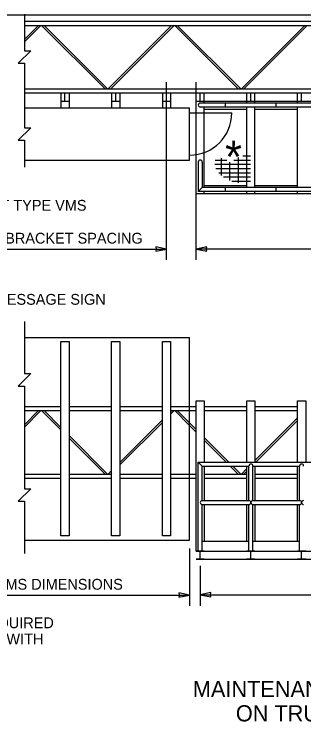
# Model space of a CAD drawing. Extents: x 99862 to 103151, y 100000 to 105076.
# Drawn here: x 100607 to 101035, y 101019 to 102077 of the extents above; entities that cross this region are included whole.
import ezdxf

# ---------------------------------------------------------------- set-up
doc = ezdxf.new("R2010")
doc.units = 0
for name, color, linetype in [('Level 1', 7, 'Continuous'), ('Level 15', 7, 'Continuous'), ('Level 18', 7, 'Continuous'), ('Level 2', 7, 'Continuous'), ('Level 20', 7, 'Continuous'), ('Level 22', 7, 'Continuous'), ('Level 23', 7, 'Continuous'), ('Level 26', 7, 'Continuous'), ('Level 27', 7, 'Continuous'), ('Level 7', 7, 'Continuous')]:
    doc.layers.add(name, color=color, linetype=linetype)

msp = doc.modelspace()

# ---------------------------------------------------------------- linework, layer by layer
at = {"layer": 'Level 1'}
msp.add_lwpolyline([(99862, 99999.5), (103151, 99999.5), (103151, 102075.5), (99862, 102075.5)], close=True, dxfattribs=at)
at = {"layer": 'Level 15'}
for p, q in [((100832, 101713.3), (100832, 101976.3)), ((100876, 101713.3), (100876, 101976.3)), ((100300.8, 101729.3), (100832, 101729.3)), ((101557, 101729.3), (100876, 101729.3)), ((100622.1, 101474), (100622.1, 101426.7)), ((100866.3, 101286.2), (100866.3, 101201)), ((100882, 101260.4), (100882, 101201)), ((100266.8, 101217), (100866.3, 101217)), ((100882, 101217.6), (101557, 101217.6))]:
    msp.add_line(p, q, dxfattribs=at)
for points in [[(100622.1, 102076.7), (100622.1, 102022.7), (100631.3, 102022.7), (100612.8, 102004.2), (100622.1, 102004.2), (100622.1, 101951.9)], [(100622.1, 101961.1), (100622.1, 101908.9), (100631.3, 101908.9), (100612.8, 101890.3), (100622.1, 101890.3), (100622.1, 101850.3)], [(100622.1, 101622.1), (100622.1, 101544.8), (100631.3, 101544.8), (100612.8, 101526.3), (100622.1, 101526.3), (100622.1, 101474)], [(100622.1, 101426.7), (100622.1, 101374.4), (100631.3, 101374.4), (100612.8, 101355.8), (100622.1, 101355.8), (100622.1, 101278.6)]]:
    msp.add_lwpolyline(points, dxfattribs=at)
for points in [[(100832, 101729.3), (100816.3, 101732.4), (100817.1, 101729.3), (100816.3, 101726.2)], [(100876, 101729.3), (100891.8, 101726.2), (100891, 101729.3), (100891.8, 101732.4)], [(100866.3, 101217), (100850.6, 101220.1), (100851.3, 101217), (100850.6, 101213.9)], [(100882, 101217.6), (100897.8, 101214.5), (100897, 101217.6), (100897.8, 101220.6)]]:
    msp.add_lwpolyline(points, close=True, dxfattribs=at)
at = {"layer": 'Level 18'}
for p, q in [((100876, 101948.3), (100876, 101960.3)), ((100888, 101948.3), (100888, 101960.3)), ((100951, 101948.3), (100951, 101960.3)), ((100963, 101948.3), (100963, 101960.3)), ((101026, 101948.3), (101026, 101960.3))]:
    msp.add_line(p, q, dxfattribs=at)
at = {"layer": 'Level 2'}
for p, q in [((100676, 101960.3), (100676, 101938.3)), ((100688, 101960.3), (100688, 101938.3)), ((100751, 101960.3), (100751, 101938.3)), ((100763, 101960.3), (100763, 101938.3)), ((100826, 101960.3), (100826, 101938.3)), ((100838, 101960.3), (100838, 101938.3)), ((100876, 101811.3), (100876, 101948.3)), ((100876, 101948.3), (101563, 101948.3)), ((100888, 101945.3), (100888, 101948.3)), ((100951, 101945.3), (100951, 101948.3)), ((100963, 101945.3), (100963, 101948.3)), ((101026, 101945.3), (101026, 101948.3)), ((100622.1, 101938.3), (100866.3, 101938.3)), ((100866.3, 101860.8), (100866.3, 101938.3)), ((101507.3, 101945.3), (100882, 101945.3)), ((101507.3, 101939.3), (100882, 101939.3)), ((100888, 101820.4), (100888, 101939.3)), ((100888, 101936.3), (100951, 101936.3)), ((100919.5, 101939.3), (100919.5, 101945.3)), ((100951, 101820.4), (100951, 101939.3)), ((100963, 101820.4), (100963, 101939.3)), ((100963, 101936.3), (101026, 101936.3)), ((100994.5, 101939.3), (100994.5, 101945.3)), ((101026, 101820.4), (101026, 101939.3)), ((100866.3, 101930.8), (100928.8, 101930.8)), ((100622.1, 101860.8), (100866.3, 101860.8)), ((100879, 101858), (100879, 101814.4)), ((100885, 101858), (100885, 101820.4)), ((100885, 101820.4), (100879, 101814.4)), ((101554.1, 101820.4), (100885, 101820.4)), ((100888, 101823.3), (100951, 101823.3)), ((100919.5, 101814.4), (100919.5, 101820.4)), ((100963, 101823.3), (101026, 101823.3)), ((100994.5, 101814.4), (100994.5, 101820.4)), ((100876, 101811.3), (101563, 101811.3)), ((101560.1, 101814.4), (100879, 101814.4)), ((100888, 101811.3), (100888, 101814.4)), ((100951, 101811.3), (100951, 101814.4)), ((100963, 101811.3), (100963, 101814.4)), ((101026, 101811.3), (101026, 101814.4)), ((100622.1, 101598.5), (100866.3, 101598.5)), ((100866.3, 101298.5), (100866.3, 101598.5)), ((100879, 101414), (100885, 101408)), ((100622.1, 101298.5), (100866.3, 101298.5))]:
    msp.add_line(p, q, dxfattribs=at)
for points in [[(100676, 101592.5), (100688, 101592.5), (100688, 101304.5), (100676, 101304.5)], [(100751, 101592.5), (100763, 101592.5), (100763, 101304.5), (100751, 101304.5)], [(100826, 101592.5), (100838, 101592.5), (100838, 101304.5), (100826, 101304.5)]]:
    msp.add_lwpolyline(points, close=True, dxfattribs=at)
for centre, radius, start, end in [((100882, 101942.3), 3, 90, 270), ((100866.3, 101930.8), 62.5, 270, 0), ((100882, 101858), 3, 0, 180), ((100957, 101408), 3, 0, 180), ((101032, 101408), 3, 0, 180), ((100885, 101354), 3, 90, 270), ((100954, 101354), 3, 270, 90), ((100960, 101354), 3, 90, 270), ((101029, 101354), 3, 270, 90), ((101035, 101354), 3, 90, 270)]:
    msp.add_arc(centre, radius, start, end, dxfattribs=at)
at = {"layer": 'Level 22'}
for points in [[(100888, 101282), (100876, 101282), (100876, 101504.5), (100888, 101504.5), (100888, 101414)], [(100951, 101414), (100951, 101504.5), (100963, 101504.5), (100963, 101414)], [(101026, 101414), (101026, 101504.5), (101038, 101504.5), (101038, 101414)], [(100888, 101408), (100888, 101357)], [(100951, 101357), (100951, 101408)], [(100963, 101408), (100963, 101357)], [(101026, 101357), (101026, 101408)], [(100888, 101351), (100888, 101297)], [(100951, 101297), (100951, 101351)], [(100963, 101351), (100963, 101297)], [(101026, 101297), (101026, 101351)]]:
    msp.add_lwpolyline(points, dxfattribs=at)
at = {"layer": 'Level 23'}
for p, q in [((100676, 101960.3), (100688, 101960.3)), ((100682, 101948.3), (100682, 101960.3)), ((100751, 101960.3), (100763, 101960.3)), ((100757, 101948.3), (100757, 101960.3)), ((100826, 101960.3), (100838, 101960.3)), ((100832, 101948.3), (100832, 101960.3)), ((100876, 101960.3), (100888, 101960.3)), ((100882, 101948.3), (100882, 101960.3)), ((100951, 101960.3), (100963, 101960.3)), ((100957, 101948.3), (100957, 101960.3)), ((101026, 101960.3), (101038, 101960.3)), ((101032, 101948.3), (101032, 101960.3)), ((100676, 101948.3), (100688, 101948.3)), ((100751, 101948.3), (100763, 101948.3)), ((100826, 101948.3), (100838, 101948.3)), ((100876, 101948.3), (100888, 101948.3)), ((100951, 101948.3), (100963, 101948.3)), ((101026, 101948.3), (101038, 101948.3)), ((100888, 101282), (100876, 101282)), ((100882, 101270), (100882, 101282)), ((100963, 101282), (100951, 101282)), ((100957, 101270), (100957, 101282)), ((101038, 101282), (101026, 101282)), ((101032, 101270), (101032, 101282)), ((100888, 101270), (100876, 101270)), ((100963, 101270), (100951, 101270)), ((101038, 101270), (101026, 101270))]:
    msp.add_line(p, q, dxfattribs=at)
at = {"layer": 'Level 26'}
for p, q in [((100904, 101860.9), (100921.3, 101860.9)), ((100913.5, 101838.2), (100913.5, 101863.8)), ((100931.7, 101860.9), (100956.3, 101860.9)), ((100938.5, 101827.1), (100938.5, 101864.6)), ((100945, 101867.1), (100956.3, 101867.1)), ((100951, 101827.1), (100951, 101870.2)), ((100903.4, 101854.7), (100956.3, 101854.7)), ((100926, 101830.8), (100926, 101857.9)), ((100905.3, 101848.4), (100956.3, 101848.4)), ((100909.5, 101842.2), (100956.3, 101842.2)), ((100916.5, 101835.9), (100956.3, 101835.9)), ((100928.7, 101829.7), (100956.3, 101829.7))]:
    msp.add_line(p, q, dxfattribs=at)
at = {"layer": 'Level 27'}
for p, q in [((100879, 101282), (100879, 101414)), ((100879, 101414), (101250.4, 101414)), ((100885, 101408), (100954, 101408)), ((100885, 101357), (100885, 101408)), ((100954, 101357), (100954, 101408)), ((100960, 101408), (101029, 101408)), ((100960, 101357), (100960, 101408)), ((101029, 101357), (101029, 101408)), ((100885, 101357), (100954, 101357)), ((100960, 101357), (101029, 101357)), ((100885, 101282), (100885, 101351)), ((100885, 101351), (100954, 101351)), ((100954, 101282), (100954, 101351)), ((100960, 101351), (101029, 101351)), ((100960, 101282), (100960, 101351)), ((101029, 101282), (101029, 101351)), ((100885, 101297), (100954, 101297)), ((100960, 101297), (101029, 101297)), ((100876, 101282), (101563, 101282)), ((100876, 101270), (101563, 101270))]:
    msp.add_line(p, q, dxfattribs=at)
at = {"layer": 'Level 7'}
for p, q in [((100622.1, 102066.6), (102322.6, 102066.6)), ((100622.1, 102060.3), (102322.6, 102060.3)), ((100642.8, 102060.3), (100622.1, 102039.6)), ((100646.5, 102060.3), (100622.1, 102035.9)), ((100647.5, 102060.3), (100741.3, 101966.6)), ((100651.2, 102060.3), (100744.9, 101966.6)), ((100839.7, 102060.3), (100746, 101966.6)), ((100843.4, 102060.3), (100749.7, 101966.6)), ((100844.5, 102060.3), (100938.2, 101966.6)), ((100848.1, 102060.3), (100941.9, 101966.6)), ((101036.7, 102060.3), (100942.9, 101966.6)), ((101040.4, 102060.3), (100946.6, 101966.6)), ((100622.1, 101966.6), (102322.6, 101966.6)), ((100622.1, 101960.3), (102322.6, 101960.3)), ((100622.1, 101496.2), (100676, 101496.2)), ((100688, 101496.2), (100751, 101496.2)), ((100763, 101496.2), (100826, 101496.2)), ((100838, 101496.2), (100866.3, 101496.2)), ((100866.3, 101496.2), (100876, 101496.2)), ((100888, 101496.2), (100951, 101496.2)), ((100963, 101496.2), (101026, 101496.2)), ((100646.5, 101490), (100622.1, 101465.5)), ((100642.8, 101490), (100622.1, 101469.2)), ((100622.1, 101490), (100676, 101490)), ((100647.5, 101490), (100676, 101461.4)), ((100651.2, 101490), (100676, 101465.1)), ((100688, 101490), (100751, 101490)), ((100763, 101490), (100826, 101490)), ((100843.4, 101490), (100838, 101484.6)), ((100839.7, 101490), (100838, 101488.3)), ((100838, 101490), (100866.3, 101490)), ((100844.5, 101490), (100866.3, 101468.1)), ((100848.1, 101490), (100866.3, 101471.8)), ((100866.3, 101490), (100876, 101490)), ((100888, 101490), (100951, 101490)), ((100963, 101490), (101026, 101490)), ((100826, 101476.3), (100763, 101413.3)), ((100826, 101472.6), (100763, 101409.6)), ((100866.3, 101471.8), (100876, 101462.1)), ((101026, 101479.3), (100963, 101416.3)), ((101026, 101475.6), (100964.4, 101414)), ((100866.3, 101468.1), (100876, 101458.4)), ((100688, 101453.1), (100744.9, 101396.2)), ((100688, 101449.4), (100741.3, 101396.2)), ((100888, 101450.1), (100924.1, 101414)), ((100888, 101446.4), (100920.4, 101414)), ((100926.4, 101408), (100938.2, 101396.2)), ((100930.1, 101408), (100941.9, 101396.2)), ((100622.1, 101396.2), (100676, 101396.2)), ((100688, 101396.2), (100751, 101396.2)), ((100751, 101401.3), (100746, 101396.2)), ((100751, 101397.6), (100749.7, 101396.2)), ((100763, 101396.2), (100826, 101396.2)), ((100838, 101396.2), (100866.3, 101396.2)), ((100866.3, 101396.2), (100876, 101396.2)), ((100888, 101396.2), (100951, 101396.2)), ((100951, 101404.3), (100942.9, 101396.2)), ((100951, 101400.6), (100946.6, 101396.2)), ((100963, 101396.2), (101026, 101396.2)), ((100622.1, 101390), (100676, 101390)), ((100688, 101390), (100751, 101390)), ((100763, 101390), (100826, 101390)), ((100838, 101390), (100866.3, 101390)), ((100866.3, 101390), (100876, 101390)), ((100888, 101390), (100951, 101390)), ((100963, 101390), (101026, 101390))]:
    msp.add_line(p, q, dxfattribs=at)

# ---------------------------------------------------------------- texts
at = {"layer": 'Level 20'}
for s, height, p in [('*', 48, (100918.8, 101841.8)), ('WALK-IN CABINET TYPE VMS', 16, (100411.9, 101786)), ('3\' - 0" MAX. ATTACHMENT BRACKET SPACING', 16, (100322.8, 101737.3)), ('TOP OF VARIABLE MESSAGE SIGN', 16, (100382, 101646.8)), ('SEE CONTRACT FOR VMS DIMENSIONS', 16, (100355.1, 101225)), ('WALKWAY IN THIS ZONE IS REQUIRED', 16, (100263.7, 101168)), ('FOR VARIABLE MESSAGE SIGN WITH', 16, (100263.7, 101144)), ('MAINTENANCE WALKWAY INSTALLED', 24, (100871.1, 101066)), ('ON TRUSS-TYPE SIGN BRIDGE', 24, (100934.7, 101030))]:
    msp.add_text(s, height=height, dxfattribs=at).set_placement(p)

doc.saveas('drawing.dxf')
